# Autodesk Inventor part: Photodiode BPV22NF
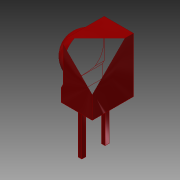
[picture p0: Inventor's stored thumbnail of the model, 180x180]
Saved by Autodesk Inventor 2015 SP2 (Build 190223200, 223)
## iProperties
Created: 2012-08
Part Number: Photodiode BPV22NF
Material: PC/ABS-Kunststoff
Document SubType Name: Modeling
Designer: rYan
Mass: 0.15883 g
Surface Area: 1.49802 cm^2
Volume: 0.106383 cm^3
Density: 1.493 g/cm^3
Appearance: Rot
Author: rYan
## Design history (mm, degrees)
sketch "Skizze1"
  geometry: L1 (0, 0)-(0, 6); L2 (0, 6)-(3.2, 6); L3 (3.2, 6)-(3.2, 1.8); L4 (3.2, 1.8)-(3.4, 1.4); L5 (3.4, 1.4)-(3.4, 0); L6 (3.4, 0)-(0, 0)
  constraints: 12 end point, 2 parallel, 2 perpendicular, 1 vertical
  dimensions: "d0" = 3.4 distance of L5.end L1.start; "d1" = 6 distance of L1.start L1.end; "d2" = 3.2 distance of L1.end L2.end; "d5" = 4.2 distance of L2.end L3.end; "d6" = 1.4 distance of L4.end L5.end
extrude "Extrusion1" new body sketch "Skizze1" stored distance "d7" = 4.5; taper "d8" = 0 deg
sketch "Skizze3"
  geometry: L1 (0, 6)-(3.2, 6) reference; L2 (0, 0)-(0, 6) reference; L3 (3.2, 6)-(3.2, 1.8) reference; L4 (5, 5.856)-(5, 1.8); L5 (2.75, 1.35)-(2.75, 5.85); A1 r 2.25 centre (2.75, 3.6) between (2.75, 1.35) and (2.75, 5.85)
  constraints: 4 end point, 2 parallel, 2 point on circle, 1 centre point, 1 midpoint, 1 tangent
  dimensions: "d12" = 4.5 diameter of A1; "d13" = 5 distance between parallel lines of L4 L2; "d14" = 2.4 distance from line of L1 A1.centre
revolve "Umdrehung1" sketch "Skizze3" stored, may be unused: angle "d15" = 90 deg
sketch "Skizze4"
  geometry: L1 (1.9, -0.755)-(2.3, -0.755); L2 (2.3, -0.755)-(2.3, -1.205); L3 (2.3, -1.205)-(1.9, -1.205); L4 (1.9, -1.205)-(1.9, -0.755); L5 (1.9, -3.295)-(2.3, -3.295); L6 (2.3, -3.295)-(2.3, -3.745); L7 (2.3, -3.745)-(1.9, -3.745); L8 (1.9, -3.745)-(1.9, -3.295); L9 (3.4, 0)-(3.4, -4.5) reference; L10 (0, 0)-(3.4, 0) reference; L11 (0, -4.5)-(0, 0) reference; L12 (3.4, -4.5)-(0, -4.5) reference; L13 (0, -2.25)-(3.4, -2.25)
  constraints: 18 end point, 4 parallel, 2 horizontal, 2 perpendicular, 1 midpoint, 4 other
  dimensions: "d16" = 0.4 distance of L1.start L1.end; "d18" = 0.45 distance of L3.end L1.start; "d19" = 2.09 distance between parallel lines of L3 L5; "d20" = 1.1 distance between parallel lines of L2 L9
extrude "Extrusion2" join sketch "Skizze4" distance "d21" = 5; taper "d22" = 0 deg
node "Volumenkörper1"
node "Projizierte Kontur1"
